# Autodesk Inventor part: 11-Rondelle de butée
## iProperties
Created: 2011-02
Part Number: 11-Rondelle de butée
Document SubType Name: Modeling
Designer: eric
Density: 1 g/cm^3
Author: eric
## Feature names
1. Base1
